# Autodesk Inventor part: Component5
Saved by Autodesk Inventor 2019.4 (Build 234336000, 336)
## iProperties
Created: 2020-02
Part Number: Component5
Material: Generic
Document SubType Name: Modeling
Designer: Administrator
Density: 1 g/cm^3
Appearance: Default
Title: Component5
Author: Administrator
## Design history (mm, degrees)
feature "Body1"
body "Solid1"
